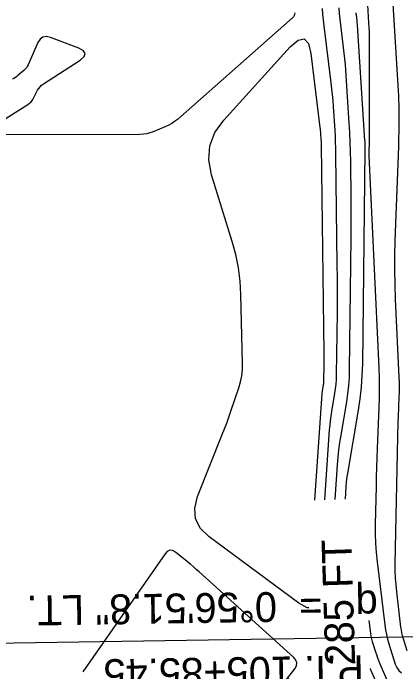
# Model space of a CAD drawing. Extents: x 1768942 to 1774819, y 723037 to 732099.
# Drawn here: x 1770703.8 to 1770782.8, y 724815.1 to 724947.7 of the extents above; entities that cross this region are included whole.
import ezdxf

# ---------------------------------------------------------------- set-up
doc = ezdxf.new("R2010")
doc.units = 0
for name, color, linetype in [('R_Contour Annot', 7, 'Continuous'), ('R_Contours', 7, 'Continuous'), ('R_Horz Alg', 7, 'Continuous'), ('R_Horz Alg Annot', 7, 'Continuous')]:
    doc.layers.add(name, color=color, linetype=linetype)

msp = doc.modelspace()

# ---------------------------------------------------------------- linework, layer by layer
at = {"layer": 'R_Contours'}
for points in [[(1770779.51, 724960.43), (1770781.27, 724932.03), (1770781.32, 724931.1), (1770781.35, 724930.16), (1770781.37, 724929.23), (1770781.38, 724928.29), (1770781.38, 724924.55), (1770781.38, 724923.62), (1770781.36, 724922.68), (1770781.34, 724921.75), (1770781.31, 724920.81), (1770780.61, 724901.87), (1770780.53, 724898.92), (1770780.51, 724895.98), (1770780.56, 724893.03), (1770780.66, 724890.09), (1770781.39, 724874.42), (1770781.43, 724873.43), (1770781.44, 724872.43), (1770781.43, 724871.43), (1770781.4, 724870.43), (1770781.24, 724866.43), (1770781.2, 724865.43), (1770781.17, 724864.43), (1770781.14, 724863.44), (1770781.12, 724862.44), (1770780.62, 724836.79), (1770780.62, 724835.4), (1770780.67, 724834.02), (1770780.76, 724832.64), (1770780.9, 724831.25), (1770781.76, 724824.14), (1770781.85, 724823.56), (1770781.96, 724822.99), (1770782.09, 724822.42), (1770782.25, 724821.86), (1770783.01, 724819.42)], [(1770775.1, 724949.36), (1770775.32, 724945.71), (1770775.37, 724944.8), (1770775.41, 724943.88), (1770775.43, 724942.97), (1770775.43, 724942.06), (1770775.43, 724922.39), (1770775.43, 724922.1), (1770775.43, 724921.82), (1770775.42, 724921.53), (1770775.41, 724921.25), (1770775.37, 724920.11), (1770775.36, 724919.82), (1770775.36, 724919.54), (1770775.37, 724919.25), (1770775.38, 724918.97), (1770777.35, 724876.31), (1770777.43, 724874.3), (1770777.45, 724872.3), (1770777.44, 724870.3), (1770777.38, 724868.29), (1770777.04, 724860.08), (1770776.97, 724858.17), (1770776.9, 724856.27), (1770776.85, 724854.36), (1770776.81, 724852.45), (1770776.66, 724844.83), (1770776.66, 724842.92), (1770776.72, 724841.02), (1770776.85, 724839.13), (1770777.05, 724837.23), (1770778.58, 724824.57), (1770778.72, 724823.61), (1770778.9, 724822.65), (1770779.13, 724821.71), (1770779.4, 724820.77), (1770780.66, 724816.7), (1770780.96, 724816), (1770781.39, 724815.42), (1770781.94, 724814.96)], [(1770766.47, 724849.71), (1770767.47, 724863.8), (1770767.54, 724864.73), (1770767.64, 724865.65), (1770767.77, 724866.58), (1770767.91, 724867.5), (1770768.54, 724871.17), (1770768.68, 724872.09), (1770768.78, 724873.02), (1770768.84, 724873.94), (1770768.87, 724874.88), (1770769.02, 724887.36), (1770769.04, 724889.76), (1770769.04, 724892.15), (1770769.04, 724894.54), (1770769.01, 724896.93), (1770768.73, 724919.26), (1770768.71, 724920.46), (1770768.67, 724921.67), (1770768.62, 724922.87), (1770768.55, 724924.07), (1770768.23, 724928.87), (1770768.15, 724930.07), (1770768.04, 724931.27), (1770767.92, 724932.46), (1770767.78, 724933.66), (1770766.37, 724945.12), (1770766.23, 724946.28), (1770766.11, 724947.44), (1770766.01, 724948.6)], [(1770768.56, 724849.77), (1770768.62, 724850.81), (1770769.05, 724856.81), (1770769.17, 724858.3), (1770769.33, 724859.79), (1770769.53, 724861.28), (1770769.76, 724862.76), (1770770.91, 724869.48), (1770771.15, 724871.09), (1770771.33, 724872.71), (1770771.44, 724874.34), (1770771.49, 724875.97), (1770771.8, 724902.43), (1770771.82, 724904.36), (1770771.82, 724906.28), (1770771.82, 724908.21), (1770771.8, 724910.14), (1770771.7, 724917.85), (1770771.66, 724919.77), (1770771.6, 724921.7), (1770771.51, 724923.62), (1770771.4, 724925.55), (1770770.71, 724936.21), (1770770.63, 724937.35), (1770770.53, 724938.49), (1770770.41, 724939.63), (1770770.28, 724940.77), (1770769.72, 724945.31), (1770769.59, 724946.45), (1770769.47, 724947.58), (1770769.37, 724948.72)], [(1770760.43, 724947.7), (1770760.39, 724947.42), (1770760.3, 724947.16), (1770760.16, 724946.93), (1770759.96, 724946.73), (1770736.81, 724926.29), (1770736.27, 724925.86), (1770735.71, 724925.47), (1770735.12, 724925.14), (1770734.5, 724924.85), (1770731.94, 724923.8), (1770731.3, 724923.57), (1770730.64, 724923.4), (1770729.97, 724923.3), (1770729.29, 724923.26), (1770700.04, 724923.15)], [(1770770.63, 724849.84), (1770770.81, 724852.44), (1770770.88, 724853.19), (1770770.96, 724853.94), (1770771.06, 724854.68), (1770771.17, 724855.43), (1770773.28, 724867.78), (1770773.62, 724870.09), (1770773.88, 724872.41), (1770774.04, 724874.74), (1770774.12, 724877.07), (1770774.62, 724920.09), (1770774.62, 724920.25), (1770774.62, 724920.42), (1770774.62, 724920.58), (1770774.62, 724920.75), (1770774.61, 724921.41), (1770774.6, 724921.57), (1770774.6, 724921.73), (1770774.59, 724921.9), (1770774.58, 724922.06), (1770773.08, 724945.22), (1770773.06, 724945.47), (1770773.04, 724945.72), (1770773.01, 724945.97), (1770772.99, 724946.22), (1770772.86, 724947.23), (1770772.83, 724947.48), (1770772.81, 724947.73)], [(1770699.56, 724924.79), (1770706.7, 724929.27), (1770707.05, 724929.53), (1770707.37, 724929.83), (1770707.64, 724930.17), (1770707.86, 724930.55), (1770708.68, 724932.14), (1770708.9, 724932.52), (1770709.17, 724932.86), (1770709.48, 724933.16), (1770709.84, 724933.43), (1770717.22, 724938.22), (1770718.04, 724938.91), (1770718.27, 724939.54), (1770717.91, 724940.1), (1770716.96, 724940.6), (1770711.26, 724942.76), (1770710.45, 724942.94), (1770709.76, 724942.83), (1770709.2, 724942.42), (1770708.75, 724941.72), (1770706.78, 724937.28), (1770706.61, 724936.95), (1770706.41, 724936.65), (1770706.18, 724936.37), (1770705.91, 724936.12), (1770704.79, 724935.17), (1770704.5, 724934.94), (1770704.2, 724934.73), (1770703.88, 724934.53), (1770703.56, 724934.36)], [(1770763.26, 724827.99), (1770762.93, 724827.99), (1770761.26, 724828.94), (1770743.2, 724842.3), (1770741.45, 724843.99), (1770740.49, 724845.9), (1770740.3, 724848.03), (1770740.89, 724850.39), (1770745.84, 724862.85), (1770746.29, 724864.01), (1770746.74, 724865.19), (1770747.16, 724866.37), (1770747.57, 724867.55), (1770749.18, 724872.3), (1770749.53, 724873.5), (1770749.77, 724874.71), (1770749.9, 724875.94), (1770749.93, 724877.19), (1770749.6, 724891.04), (1770749.45, 724893.75), (1770749.11, 724896.43), (1770748.58, 724899.08), (1770747.86, 724901.7), (1770743.71, 724915.11), (1770743.14, 724918.13), (1770743.36, 724920.97), (1770744.36, 724923.64), (1770746.15, 724926.13), (1770759.54, 724940.86), (1770761.11, 724942.23), (1770762.32, 724942.46), (1770763.18, 724941.57), (1770763.68, 724939.55), (1770765.52, 724924.64), (1770765.55, 724924.34), (1770765.58, 724924.04), (1770765.61, 724923.74), (1770765.63, 724923.44), (1770765.71, 724922.24), (1770765.73, 724921.93), (1770765.74, 724921.63), (1770765.75, 724921.33), (1770765.76, 724921.03), (1770766.28, 724879.19), (1770766.29, 724878.6), (1770766.29, 724878.02), (1770766.29, 724877.43), (1770766.29, 724876.84), (1770766.25, 724873.78), (1770766.24, 724873.55), (1770766.23, 724873.32), (1770766.2, 724873.09), (1770766.17, 724872.87), (1770766.01, 724871.97), (1770765.98, 724871.74), (1770765.95, 724871.51), (1770765.92, 724871.29), (1770765.91, 724871.06), (1770764.39, 724849.64)], [(1770758.04, 724812.65), (1770760.43, 724815.73), (1770760.78, 724816.33), (1770760.86, 724816.91), (1770760.68, 724817.46), (1770760.23, 724817.99), (1770741.2, 724835.24), (1770740.63, 724835.75), (1770740.04, 724836.26), (1770739.45, 724836.76), (1770738.85, 724837.24), (1770736.43, 724839.18), (1770735.84, 724839.52), (1770735.3, 724839.58), (1770734.79, 724839.37), (1770734.33, 724838.87), (1770717.78, 724815.12)], [(1770775.34, 724825.45), (1770775.6, 724823.37), (1770775.67, 724822.83), (1770775.78, 724822.3), (1770775.9, 724821.77), (1770776.05, 724821.24), (1770776.7, 724819.15), (1770776.87, 724818.63), (1770777.05, 724818.12), (1770777.25, 724817.61), (1770777.46, 724817.1), (1770778.93, 724813.64)], [(1770776.94, 724812.79), (1770775.92, 724815.19), (1770775.85, 724815.36), (1770775.77, 724815.53), (1770775.7, 724815.69), (1770775.66, 724815.78)]]:
    msp.add_lwpolyline(points, dxfattribs=at)
at = {"layer": 'R_Horz Alg'}
msp.add_lwpolyline([(1770821.12, 724822.68), (1770656.14, 724820.14)], dxfattribs=at)

# ---------------------------------------------------------------- texts
at = {"layer": 'R_Contour Annot'}
msp.add_text('285 FT', height=6, rotation=91.8409, dxfattribs=at).set_placement((1770772.63, 724816.46))
at = {"layer": 'R_Horz Alg Annot'}
for s, p in [('q   =  0%%d56\'51.8" LT.', (1770777.11, 724831.51)), ('P.I. 105+85.45', (1770774.31, 724818.46))]:
    msp.add_text(s, height=6, rotation=180.8827, dxfattribs=at).set_placement(p)

doc.saveas('drawing.dxf')
